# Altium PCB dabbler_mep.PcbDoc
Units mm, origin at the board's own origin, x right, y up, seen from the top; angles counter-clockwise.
Board outline 28 x 70 mm, 2 copper layers (Top Layer, Bottom Layer); 52 components, 40 nets, 219 pads, 126 vias.
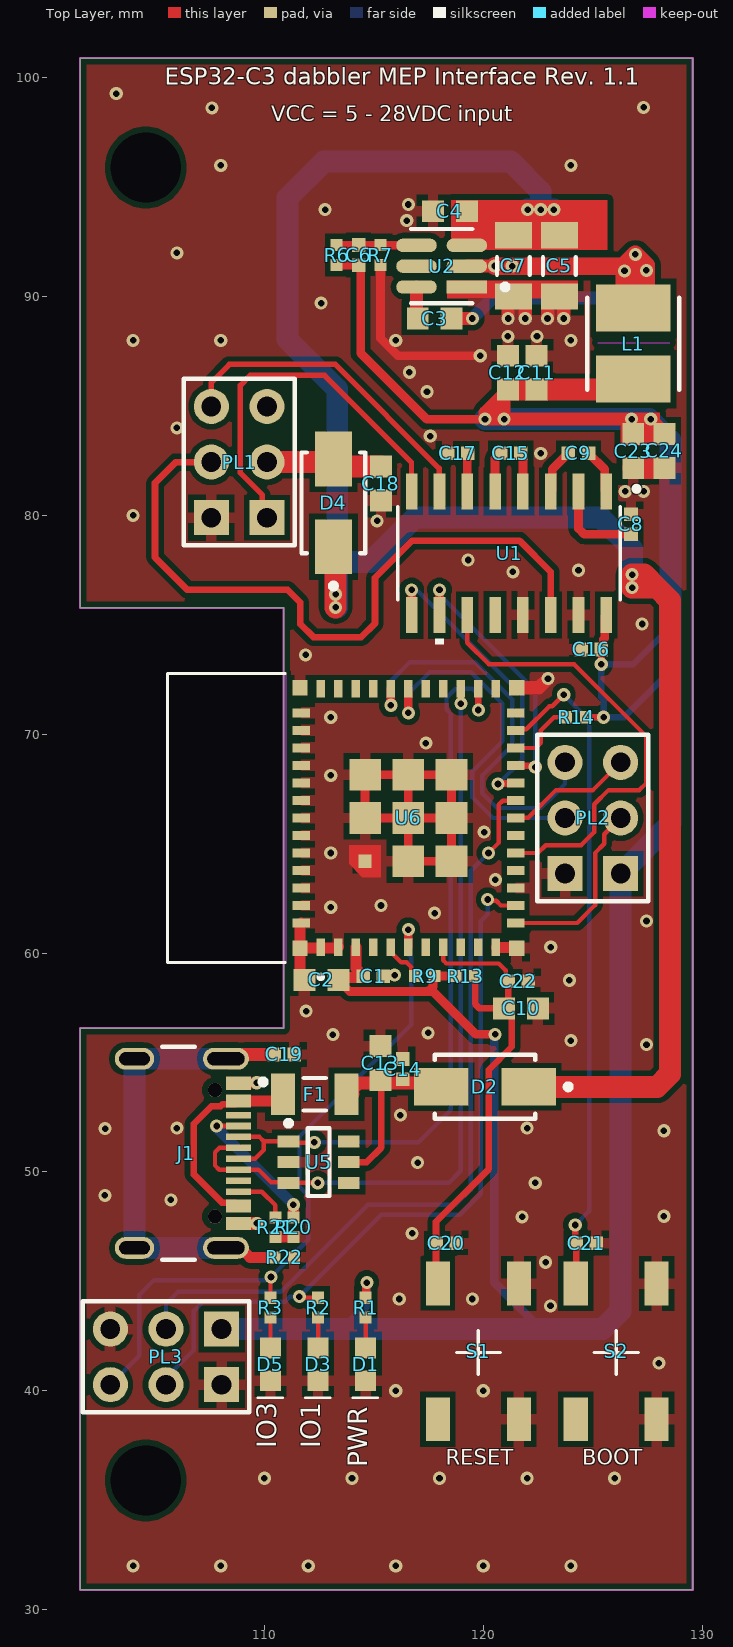
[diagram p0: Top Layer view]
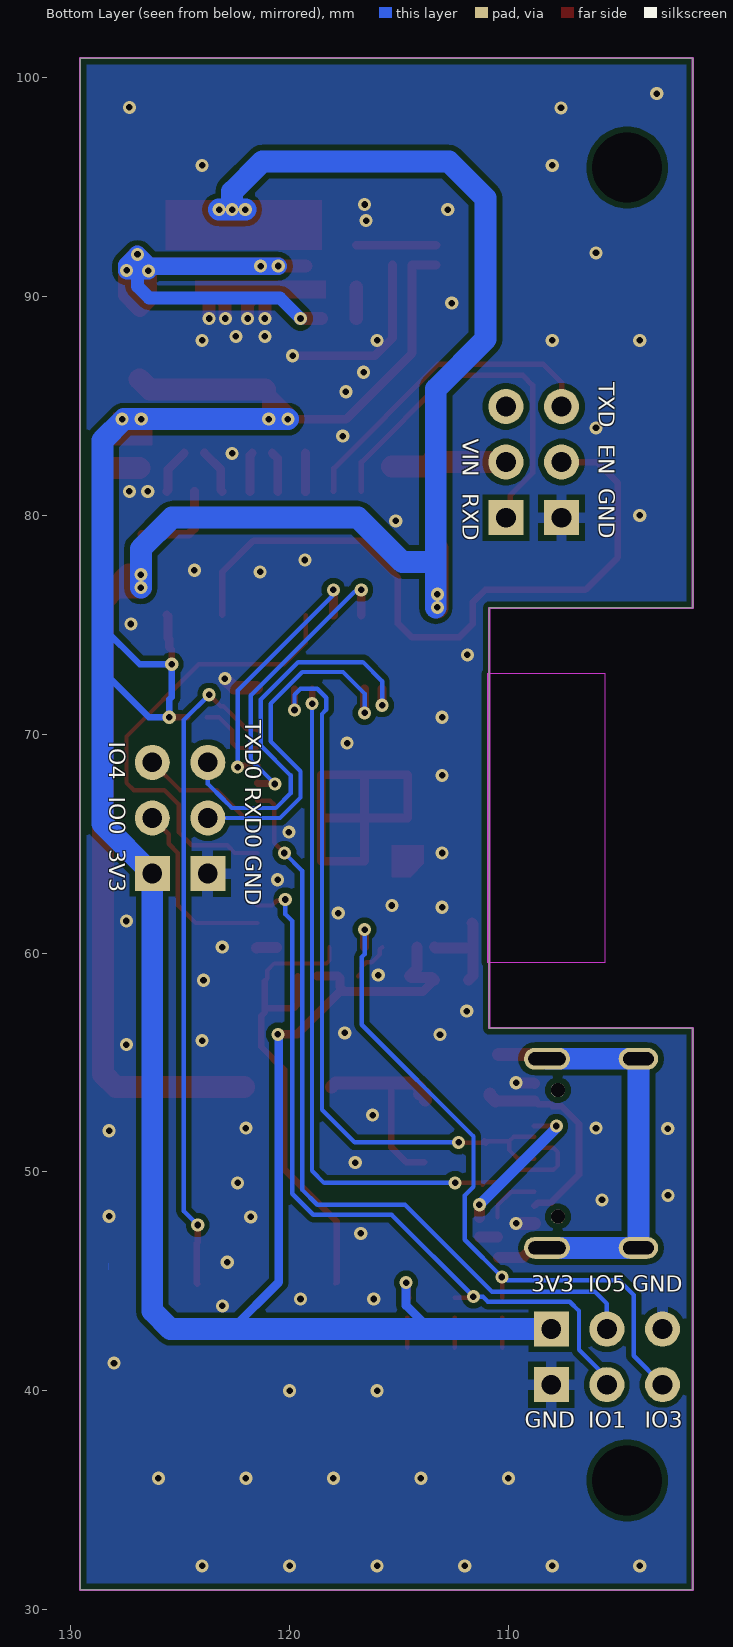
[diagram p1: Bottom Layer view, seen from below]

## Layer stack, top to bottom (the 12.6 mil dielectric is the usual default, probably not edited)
Top Solder: solder mask 0.0102, Solder Resist, Dk 3.5
Top Layer: signal copper 0.0356
Dielectric 1: dielectric 0.32, FR-4, Dk 4.8
Bottom Layer: signal copper 0.0356
Bottom Solder: solder mask 0.0102, Solder Resist, Dk 3.5

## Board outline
101.575,75.775 110.875,75.775 110.875,56.575 101.575,56.575 101.575,30.9 129.575,30.9 129.575,100.9 101.575,100.9

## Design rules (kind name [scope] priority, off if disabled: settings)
Clearance [All] p1: gap=0.254 ignorepadtopadclearanceinfootprint=FALSE except(0: Arc-Hole Track-Hole SMDPad-Hole THPad-Hole Via-Hole Fill-Hole Poly-Hole Region-Hole Text-Hole; 0.2: Arc-SMDPad Arc-THPad Track-SMDPad Track-THPad SMDPad-SMDPad SMDPad-THPad)
PlaneConnect [All] p1: planeconnectstyle=Relief reliefexpansion=0.508 reliefentries=4 reliefconductorwidth=0.5 reliefairgap=0.254
PolygonConnect PolygonConnect_2 [IsVia] p1: connectstyle=Direct reliefconductorwidth=0.254 reliefentries=4 polygonreliefangle="90 Angle" airgapwidth=0.254
PolygonConnect PolygonConnect_1 [(InNet('VBUS') OR InNet('NetF1_2'))] p2: connectstyle=Direct reliefconductorwidth=0.254 reliefentries=4 polygonreliefangle="90 Angle" airgapwidth=0.254
PolygonConnect [All] p3: connectstyle=Relief reliefconductorwidth=0.5 reliefentries=4 polygonreliefangle="90 Angle" airgapwidth=0.254
RoutingVias [All] p1: holewidth=0.711 width=1.27 viastyle="Through Hole" minholewidth=0.711 minwidth=1.27 maxholewidth=0.711 maxwidth=1.27
SolderMaskExpansion [All] p1: expansion=0.102 istentingtop=FALSE
Width [All] p1: maxlimit=1 minlimit=0.2 preferedwidth=0.25 minimp=50.000000 maximp=50.000000 favimp=50.000000
29 further rules are at their usual default settings.

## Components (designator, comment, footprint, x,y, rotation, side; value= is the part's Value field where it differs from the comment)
C1 "0.1uF 0402 10V" CAP_0402 114.975,58.95 r180 top value="100 nF"
C2 "22uF 0603" CAP_0603 112.6,58.775 r0 top value=22uF
C3 "0.1uF 0603 100V" CAP_0603 117.777,89 r180 top value=0.1uF
C4 "0.1uF 0603 100V" CAP_0603 118.477,93.9 r0 top value=0.1uF
C5 "10uF 1206 50V" CAP_1206 123.477,91.4 r90 top value=10uF
C6 "47pF 0402 50V" CAP_0402 114.302,91.9 r270 top value=47pF
C7 "10uF 1206 50V" CAP_1206 121.377,91.4 r90 top value=10uF
C8 "0.1uF 0402 10V" CAP_0402 126.75,79.6 r90 top value="100 nF"
C9 "0.1uF 0402 10V" CAP_0402 124.35,82.85 r180 top value="100 nF"
C10 "22uF 0603" CAP_0603 121.725,57.475 r180 top value=22uF
C11 "22uF 0603" CAP_0603 122.44,86.523 r270 top value=22uF
C12 "22uF 0603" CAP_0603 121.127,86.523 r270 top value=22uF
C13 "22uF 0603" CAP_0603 115.302,54.975 r270 top value=22uF
C14 "0.1uF 0402 10V" CAP_0402 116.327,54.7 r270 top value="100 nF"
C15 "0.1uF 0402 10V" CAP_0402 121.25,82.85 r180 top value="100 nF"
C16 "0.1uF 0402 10V" CAP_0402 124.929,73.875 r0 top value="100 nF"
C17 "0.1uF 0402 10V" CAP_0402 118.825,82.85 r0 top value="100 nF"
C18 "0.1uF 0603 100V" CAP_0603 115.325,81.456 r90 top value=0.1uF
C19 "47pF 0402 50V" CAP_0402 110.906,55.367 r180 top value=47pF
C20 "0.1uF 0402 10V" CAP_0402 118.3,46.75 r180 top value="100 nF"
C21 "0.1uF 0402 10V" CAP_0402 124.7,46.75 r180 top value="100 nF"
C22 "0.1uF 0402 10V" CAP_0402 121.591,58.716 r0 top value="100 nF"
C23 "22uF 0603" CAP_0603 126.852,82.941 r90 top value=22uF
C24 "22uF 0603" CAP_0603 128.275,82.95 r90 top value=22uF
D1 "GREEN LED 0603" "0603 LED" 121.606,25.208 r90 top
D2 "B340A-13-F" FP-SMA-MFG 120.077,53.89 r180 top
D3 "GREEN LED 0603" "0603 LED" 119.433,25.208 r90 top
D4 "B340A-13-F" FP-SMA-MFG 113.15,80.575 r90 top
D5 "GREEN LED 0603" "0603 LED" 117.26,25.208 r90 top
F1 "PTC 500mA Hold" "PTC Fuse 1206" 112.3,53.55 r180 top
J1 "USB4105-GF-A" FP-USB4105-GF-A-MFG 105.225,50.85 r270 top
L1 "6.8uH 1.6A" INDP4040X30N 126.852,87.852 r270 top value=6.8uH
PL1 "2x3-pin Male Header 2.54mm straight" "2x3-pin 2.54mm header" 108.845,82.44 r90 top locked
PL2 "2x3-pin Male Header 2.54mm straight" "2x3-pin 2.54mm header" 125.005,66.175 r90 top
PL3 "2x3-pin Male Header 2.54mm straight" "2x3-pin 2.54mm header" 105.5,41.55 r180 top
R1 "1k 0402" RES_0402 114.625,43.8 r90 top value=1k
R2 "1k 0402" RES_0402 112.45,43.8 r90 top value=1k
R3 "1k 0402" RES_0402 110.275,43.8 r90 top value=1k
R6 "100k 0402" RES_0402 113.302,91.9 r270 top value=100k
R7 "22k1 0402" RES_0402 115.302,91.9 r90 top value=22k1
R9 "10k 0.5% 0402" RES_0402 117.325,58.95 r0 top value=10k
R13 "10k 0.5% 0402" RES_0402 119.175,58.95 r180 top value=10k
R14 "10k 0.5% 0402" RES_0402 124.24,70.779 r0 top value=10k
R20 "4k7 0402" RES_0402 111.325,47.475 r90 top value=4k7
R21 "4k7 0402" RES_0402 110.5,47.475 r90 top value=4k7
R22 "1MOhm 0402 5%" RES_0402 110.9,46.1 r180 top value=1Mega
S1 "TACTB-64K-F" TACTB-64K-F 119.775,41.8 r90 top
S2 "TACTB-64K-F" TACTB-64K-F 126.075,41.8 r90 top
U1 "MAX3232ESE" 21-0041_S16+1_MXM-M 121.175,78.275 r270 top
U2 "TPS54302DDCR" FP-DDC0006A-IPC_A 118.098,91.391 r180 top
U5 "SRV05-" SOT95P280X145-6N 112.475,50.45 r0 top
U6 "ESP32-C3-MINI-1-N4" ESP32-C3-MINI-1-N4-Footprint-1 113.875,66.175 r90 top locked

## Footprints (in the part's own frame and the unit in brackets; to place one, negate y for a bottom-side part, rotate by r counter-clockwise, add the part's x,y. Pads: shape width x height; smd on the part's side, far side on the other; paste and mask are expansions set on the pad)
"2x3-pin 2.54mm header" [mm]
  rect 1.6x1.6 hole 0.9: 1(-2.54,1.27) 2(-2.54,-1.27)
  round 1.6 hole 0.9: 3(0,1.27) 4(0,-1.27) 5(2.54,1.27) 6(2.54,-1.27)
  silkscreen extent -3.81,-2.54 3.81,2.54, body extent -3.81,-2.54 3.81,2.54, height 9.5
21-0041_S16+1_MXM-M [mm]
  rect 1.656x0.533 smd paste+0 mask+0: 1(-2.822,4.445) 2(-2.822,3.175) 3(-2.822,1.905) 4(-2.822,0.635) 5(-2.822,-0.635) 6(-2.822,-1.905) 7(-2.822,-3.175) 8(-2.822,-4.445) 9(2.822,-4.445) 10(2.822,-3.175) 11(2.822,-1.905) 12(2.822,-0.635) 13(2.822,0.635) 14(2.822,1.905) 15(2.822,3.175) 16(2.822,4.445)
  silkscreen extent -2.12,-5.08 4.16,5.08, body extent -3.1,-4.95 3.1,4.95, height 1.76
"0603 LED" [mm] "0603 LED"
  rect 0.95x0.95 smd: 1(16.752,6.985) 2(15.252,6.985)
  silkscreen extent 14.48,6.43 14.48,7.57, body extent 15.2,6.61 16.8,7.39, height 0.7
CAP_0402 [mm] "Chip Capacitor, 2-Leads, 0402, IPC Medium Density"
  rect 0.62x0.62 smd: 1(-0.46,0) 2(0.46,0)
  body extent -0.53,-0.28 0.53,0.28, height 0.4
CAP_0603 [mm] "Chip Capacitor, 2-Leads, 0603, IPC Medium Density"
  rect 1x1 smd: 1(-0.775,0) 2(0.775,0)
  body extent -0.87,-0.48 0.87,0.48, height 0.55
CAP_1206 [mm] "Chip Capacitor, 2-Leads, 1206, IPC Medium Density"
  rect 1.2x1.7 smd: 1(-1.4,0) 2(1.4,0)
  silkscreen extent -0.4,-0.75 0.4,0.75, body extent -1.63,-0.82 1.63,0.82, height 0.7
ESP32-C3-MINI-1-N4-Footprint-1 [mm]
  rect 0.8x0.4 smd: 1(-5.9,1.3) 2(-5.9,0.5) 3(-5.9,-0.3) 4(-5.9,-1.1) 5(-5.9,-1.9) 6(-5.9,-2.7) 7(-5.9,-3.5) 8(-5.9,-4.3) 9(-5.9,-5.1) 10(-5.9,-5.9) 11(-5.9,-6.7) 25(5.9,-6.7) 26(5.9,-5.9) 27(5.9,-5.1) 28(5.9,-4.3) 29(5.9,-3.5) 30(5.9,-2.7) 31(5.9,-1.9) 32(5.9,-1.1) 33(5.9,-0.3) 34(5.9,0.5) 35(5.9,1.3)
  rect 0.4x0.8 smd: 12(-4.8,-7.6) 13(-4,-7.6) 14(-3.2,-7.6) 15(-2.4,-7.6) 16(-1.6,-7.6) 17(-0.8,-7.6) 18(0,-7.6) 19(0.8,-7.6) 20(1.6,-7.6) 21(2.4,-7.6) 22(3.2,-7.6) 23(4,-7.6) 24(4.8,-7.6) 36(4.8,2.2) 37(4,2.2) 38(3.2,2.2) 39(2.4,2.2) 40(1.6,2.2) 41(0.8,2.2) 42(0,2.2) 43(-0.8,2.2) 44(-1.6,2.2) 45(-2.4,2.2) 46(-3.2,2.2) 47(-4,2.2) 48(-4.8,2.2)
  rect 0.6x0.6 smd paste-1 mask+0: 49_1(-1.975,-0.725)
  rect 1.45x1.45 smd: 49_2(0,-0.725) 49_3(1.975,-0.725) 49_4(1.975,-2.7) 49_5(1.975,-4.675) 49_6(0,-4.675) 49_7(-1.975,-4.675) 49_8(-1.975,-2.7) 49_9(0,-2.7)
  rect 0.7x0.7 smd: 50(5.95,2.25) 51(5.95,-7.65) 52(-5.95,-7.65) 53(-5.95,2.25)
  Top Layer region: -1.25,-1.45 -2.7,-1.45 -2.7,-0.6 -2.1,0 -1.25,0
  Keep-Out Layer region: 6.6,2.9 -6.6,2.9 -6.6,8.3 6.6,8.3
  Keep-Out Layer region: 6.6,2.9 -6.6,2.9 -6.6,8.3 6.6,8.3
  silkscreen extent -7.35,1.2 6.6,8.3, body extent -6.6,-8.3 6.6,8.3, height 2.55
FP-DDC0006A-IPC_A [mm]
  rect 1.854x0.612 smd paste+0 mask+0: 1(-1.15,0.95)
  rrect100% 1.854x0.612 smd paste+0 mask+0: 2(-1.15,0) 3(-1.15,-0.95) 4(1.15,-0.95) 5(1.15,0) 6(1.15,0.95)
  silkscreen extent -3.03,-1.7 1.4,1.7, body extent -2.58,-1.95 2.58,1.95, height 0.25
FP-SMA-MFG [mm]
  rect 2.5x1.7 smd paste+0 mask+0: 1(-2,0) 2(2,0)
  silkscreen extent -3.93,-1.46 2.3,1.46, body extent -3.35,-1.56 3.35,1.56, height 0.25
FP-USB4105-GF-A-MFG [mm]
  rrect100% 1x2.1 hole 1.7 slot 0.6 at 0 deg paste-1000 mask+0: 1(-4.32,3.015) 2(4.32,3.015)
  rrect100% 1x1.8 hole 1.4 slot 0.6 at 0 deg paste-1000 mask+0: 3(-4.32,-1.165) 4(4.32,-1.165)
  round 0.65 hole 0.65 unplated paste-1000 mask+0: -(2.89,2.515) --(-2.89,2.515)
  rect 0.6x1.15 smd paste+0 mask+0: A1-B12(-3.2,3.59) A4-B9(-2.4,3.59) B1-A12(3.2,3.59) B4-A9(2.4,3.59)
  rect 0.3x1.15 smd paste+0 mask+0: A5(-1.25,3.59) A6(-0.25,3.59) A7(0.25,3.59) A8(1.25,3.59) B5(1.75,3.59) B6(0.75,3.59) B7(-0.75,3.59) B8(-1.75,3.59)
  silkscreen extent -4.86,0.11 4.86,4.84, body extent -4.96,-3.94 4.96,4.27, height 0.25
INDP4040X30N [mm] "Precision Wire Wound Inductor, 2-Leads, Body 4.00x4.00mm, IPC Medium Density"
  rect 2.15x3.4 smd: 1(-1.625,0) 2(1.625,0)
  silkscreen extent -2.1,-2.1 2.1,2.1, body extent -2.1,-2.1 2.1,2.1, height 3
"PTC Fuse 1206" [mm]
  rect 1.1x1.9 smd: 1(-1.45,0) 2(1.45,0)
  silkscreen extent -0.5,-0.74 0.5,0.74, body extent -1.62,-0.82 1.63,0.83, height 0.4
RES_0402 [mm] "Chip Resistor, 2-Leads, 0402, IPC Medium Density"
  rect 0.55x0.55 smd: 1(-0.45,0) 2(0.45,0)
  body extent -0.53,-0.28 0.53,0.28, height 0.4
SOT95P280X145-6N [mm] "SOT23, 6-Leads, Body 2.93x2.80mm, Pitch 0.95mm, IPC Medium Density"
  rect 1x0.55 smd: 1(-1.375,0.95) 2(-1.375,0) 3(-1.375,-0.95) 4(1.375,-0.95) 5(1.375,0) 6(1.375,0.95)
  silkscreen extent -1.5,-1.55 0.5,1.9, body extent -1.5,-1.53 1.5,1.53, height 1.45
TACTB-64K-F [mm] "Tactile switch"
  rect 2x1.1 smd: 1(-3.1,1.85) 2(3.1,1.85) 3(-3.1,-1.85) 4(3.1,-1.85)
  silkscreen extent -1.05,-1 0.95,1, body extent -3.32,-2.67 3.23,2.68, height 1.6

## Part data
C1 C8 C9 C14 C15 C16 C17 C20 C21 C22: library part CMP-00101-1, "0.1uF 0402 10V X7R 10%", Tolerance="10 %", Voltage="10 V"
C2 C10 C11 C12 C13 C23 C24: library part CMP-00148-1, "Cap Ceramic 22uF 6.3V X5R 20% SMD 0603 85C Cardboard T/R", Capacitance=22uF, Case Code (Imperial)=0603, Case Code (Metric)=1608, Dielectric=X5R, Max Operating Temperature=85°C, Min Operating Temperature=-55°C, Package Quantity=1, Tolerance=20%, Voltage=6.3V
C3 C4 C18: library part CMP-00012-7, "0.1uF 10% 0603 100V X7R", Current Rating=-, Tolerance=10%, Voltage=100V
C5 C7: library part CMP-00030-4, "10uF 1206 50V X5R 20%", Tolerance="+/- 20%", Voltage="50 V"
C6 C19: library part CMP-00099-1, "47pF 0402 50V X7R 5%", Tolerance=10%, Voltage=50V
D1 D3 D5: library part CMP-008-0000-1, "SMD GREEN WATER CLEAR", Mfg. Part Number=APT1608SGC
D2 D4: library part CMP-016-0019-1, "Rectifier Diode, Schottky, 1 Phase, 1 Element, 3A, 40V V(RRM), Silicon", Average Rectified Current=3A, Capacitance=250pF, Case/Package=SMA, Forward Voltage=500mV, Max Forward Surge Current (Ifsm)=80A, Max Operating Temperature=125°C, Max Repetitive Reverse Voltage (Vrrm)=40V, Max Reverse Current=500uA, Min Operating Temperature=-55°C, Package Quantity=5000
F1: library part CMP-017-0001-1, "PTC RESET FUSE 8V 500MA 1206", Case/Package=1206, Mfg. Part Number=0ZCJ0050FF2G
J1: library part CMP-003-0034-0.0, "Conn USB 2.0 Type C RCP 24 POS 0.3mm/0.5mm Solder RA SMD 24 Terminal 1 Port T/R", Flammability Rating="UL94 V-0", Insulation Color=Black, Max Operating Temperature=85°C, Min Operating Temperature=-40°C
L1: library part CMP-00146-1, "6.8UH ±20% 1.6A 117MΩ SMD,4.0X4.0X3.0MM POWER INDUCTORS ROHS", Case/Package=4x4x3mm, Current=1.6A, Mfg. Part Number=SWPA4030S6R8MT
PL1 PL3: library part CMP-003-0019-0.0
PL2: library part CMP-003-0019-0.0, "2x3 Positions Header Connector 0.100\" (2.54mm) Through Hole Gold"
R1 R2 R3: library part CMP-001-0025-3, "RES SMD 1K OHM 1% 1/16W 0402", Case/Package=0402, Mfg. Part Number=CRG0402F1K0, Power=1/16W, Tolerance=1%
R6: library part CMP-00123-1, "Res General Purpose Thick Film 0402 100K Ohm 1% 1/16W ±100ppm/°C Molded SMD Paper T/R", Case Code (Imperial)=0402, Case Code (Metric)=1005, Max Operating Temperature=155°C, Max Power Dissipation=63mW, Mfg. Part Number=RC0402FR-07100KL, Min Operating Temperature=-55°C, Package Quantity=1, Resistance=100kR, Temperature Coefficient=100ppm/°C, Tolerance=1%, Voltage=50V
R7: library part CMP-00147-1, "VISHAY - CRCW040222K1FKEDC. - D10/CRCW0402-C 100 22K1 1% ET7 E3", Case Code (Imperial)=0402, Case Code (Metric)=1005, Max Operating Temperature=155°C, Max Power Dissipation=63mW, Min Operating Temperature=-55°C, Resistance=22.1kR, Resistor Type="Thick Film", Temperature Coefficient=100ppm/°C, Tolerance=1%
R9 R13 R14: library part CMP-0001-00029-2, "RES 10K OHM 0.5% 1/16W 0402", Case/Package=0402, Manufacturer Part No.=RC0402DR-0710KL, Tolerance=0.5%
R20 R21: library part CMP-001-0029-3, "RES SMD 4.7K OHM 1% 1/16W 0402", Case/Package=0402, Mfg. Part Number=RC1005F472CS, Power=1/16W, Tolerance=1
R22: library part CMP-001-0065-1, "RES SMD 1M OHM 5% 1/16W 0402", Case/Package=0402, Mfg. Part Number=CR0402JC1MS001, Power="1/16 W", Tolerance=5%
S1 S2: library part CMP-013-0002-1, "Microswitch TACT; SPST-NO; Positions:2; 0.05A/12VDC;", Case/Package=-
U1: library part CMP-00180-1, "MAX3232 Series 5.5 V 120 kbps Surface Mount RS-232 Transceiver - SOIC-16"
U2: library part CMP-00145-0.0, "BUCK ADJ 3A 6SOT", Case/Package=SOT-23-6, Max Input Voltage=28V, Max Operating Temperature=85°C, Min Input Voltage=4.5V, Min Operating Temperature=-40°C, Min Output Voltage=596mV, Output Current=3A, Quiescent Current=40uA, Switching Frequency=400kHz
U5: library part CMP-016-0020-1, "SRV05 Series 4 Ch 3.5 pF 15 Vclamp Steering Diode/TVS Array Combo - SOT-23-6", Capacitance=3.5pF, Case/Package=SOT-23, Clamping Voltage=15V, Leakage Current=5uA, Max Operating Temperature=150°C, Min Operating Temperature=-55°C, Peak Pulse Current=5A, Peak Pulse Power=500W, Reverse Breakdown Voltage=6V, Reverse Standoff Voltage=5V, Test Current=1mA
U6: library part CMP-00162-1, "Bluetooth, WiFi 802.11b/g/n, Bluetooth v5.0 Transceiver Module 2.412GHz ~ 2.484GHz PCB Trace Surface Mount"

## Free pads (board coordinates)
  round 0 hole 3.2: 3(104.575,35.9) 3(104.575,95.9)

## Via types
v1: diameter 0.6, hole 0.3, Top Layer to Bottom Layer, tented both sides, 126 vias

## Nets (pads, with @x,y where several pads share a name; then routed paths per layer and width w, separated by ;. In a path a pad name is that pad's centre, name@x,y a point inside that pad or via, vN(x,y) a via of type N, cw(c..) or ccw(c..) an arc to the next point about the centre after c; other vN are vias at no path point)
3V3: C1.2 C2.2 C6.2 C11.2 C12.2 C16.2 C23.2 C24.2 L1.2 PL2.2 PL3.2 R1.2 R6.2 R9.2 R13.2 R14.2 U1.16 U6.3 | length 144.2
  Top Layer w0.3: R14.2 v1(125.499,70.779) ; v1(125.389,73.2) C16.2
  Top Layer w0.4: R6.2 114.292,91.45 C6.2 ; C2.2 113.91,58.24 117.466,58.24 ; C6.2@114.402,91.45 114.402,87.415 117.417,84.4 v1(120.077,84.4) ; R1.2 114.651,44.276 114.651,44.92 v1(114.677,44.946) ; R13.2 R9.2 117.7,58.875 117.7,58.474 117.466,58.24 ; v1(120.537,56.289) 119.661,56.289 117.71,58.24 117.466,58.24 ; C16.2@125.499,73.985 125.499,74.344 125.554,74.399 125.554,75.387 U1.16
  Top Layer w0.5: C2.2 113.49,58.89 114.455,58.89 C1.2 114.175,59.29 U6.3
  Top Layer w0.6: C12.2@120.952,85.25 v1(120.952,84.4) ; C12.2 120.952,85.573 C12.2@120.927,85.548 ; C23.2 126.852,83.842 126.779,83.916 v1(126.779,84.4) ; C23.2@126.852,83.725 C24.2@128.075,83.725 ; C24.2 128.075,83.925 128.075,83.979 v1(127.654,84.4) v1(126.779,84.4) ; v1(120.077,84.4) 120.927,85.25 C12.2@120.927,85.548 ; v1(120.077,84.4) v1(120.952,84.4) ; v1(120.077,84.4) 120.077,84.698 C12.2@120.927,85.548 ; v1(120.952,84.4) v1(126.779,84.4)
  Top Layer w1: C12.2 C11.2 126.374,85.748 L1.2
  Bottom Layer w0.3: 128.55,72.9 126.429,70.779 v1(125.499,70.779) 125.499,71.589 125.389,71.699 v1(125.389,73.2) 126.85,73.2 128.5,74.85 128.55,74.85
  Bottom Layer w0.4: 113.575,42.82 113.6,42.82 114.677,43.898 v1(114.677,44.946) ; v1(120.537,56.289) 120.499,56.25 120.499,56.109 120.497,56.108 120.497,44.959 122.637,42.82
  Bottom Layer w1: PL3.2 113.575,42.82 ; 113.6,42.82 122.637,42.82 125.445,42.82 126.275,43.65 PL2.2 128.55,65.91 128.55,72.9 128.55,74.85 128.55,83.425 127.575,84.4 v1(126.779,84.4) v1(120.952,84.4) v1(120.077,84.4)
D+: J1.A6 J1.B6 U5.3 U6.27 | length 35.7
  Top Layer w0.2: J1.A6 107.945,51.1 107.74,50.895 107.74,50.297 107.937,50.1 J1.B6 108.818,50.103 109.722,50.103 110.3,49.525 111.075,49.525 U5.3 ; U5.3@111.187,49.413 U5.3 ; v1(112.437,49.5) U5.3
  Top Layer w0.3: v1(118.975,71.4) U6.27
  Bottom Layer w0.2: v1(112.437,49.5) 118.425,49.5 118.975,50.05 v1(118.975,71.4)
D-: J1.A7 J1.B7 U5.1 U6.26 | length 34.6
  Top Layer w0.2: J1.A7 109.568,50.6 109.971,51.003 109.971,51.4 ; J1.B7 109.771,51.6 109.971,51.4 ; U5.1@111.032,51.332 v1@112.275,51.332 ; U5.1@111.108,51.392 U5.1 109.971,51.4
  Top Layer w0.3: U5.1@111.032,51.332 U5.1 ; U6.26 119.779,72.071 v1(119.779,71.111)
  Bottom Layer w0.2: v1(112.275,51.35) 117.029,51.35 118.521,52.842 118.521,70.929 118.321,71.129 118.321,71.671 118.735,72.084 119.502,72.084 119.779,71.808 v1(119.779,71.111)
ENA: C10.2 C20.2 C22.1 R13.1 S1.2 U6.8 | length 22.2
  Top Layer w0.2: S1.2@117.85,44.975 S1.2 ; U6.8 118.175,59.665 118.315,59.525 120.71,59.525 121.026,59.209 121.026,58.821 C22.1
  Top Layer w0.3: S1.2@117.85,44.975 117.84,44.985 C20.2 117.84,47.723 120.258,50.14 120.258,54.674 121.3,55.717 121.3,57.125 121.131,57.294 C22.1 ; R13.1 119.625,57.676 119.826,57.475 C10.2
ENABLE: PL1.3 U1.14 | length 32.2
  Top Layer w0.3: PL1.3 105.953,82.44 104.998,81.485 104.998,78.082 106.482,76.598 111.062,76.598 111.638,76.022 111.638,75.037 112.236,74.439 114.426,74.439 115.05,75.063 115.05,77.15 116.75,78.85 121.649,78.85 123.08,77.419 U1.14 U1.14@123.077,75.456
ENARS232: U1.11 U6.16 | length 21.4
  Top Layer w0.2: U1.11 119.27,74.188 120.258,73.2 124.15,73.2 127.452,69.898 127.452,67.777 127.125,67.45 125.725,67.45 125.075,66.8 125.075,65.531 124.469,64.925 122.85,64.925 122.5,64.575 U6.16
GND: C1.1 C2.1 C4.1 C5.1 C7.1 C8.2 C10.1 C11.1 C12.1 C13.1 C14.1 C16.1 C17.1 C18.1 C19.1 C20.1 C21.1 C22.2 C23.1 C24.1 D1.2 D3.2 D5.2 J1.A1-B12 J1.B1-A12 PL1.1 PL2.1 PL3.1 PL3.6 R7.1 R20.1 R21.1 R22.1 S1.3 S1.4 S2.3 S2.4 U1.13 U1.15 U2.1 U5.2 U6.1 U6.2 U6.11 U6.14 U6.36 U6.37 U6.38 U6.39 U6.40 U6.41 U6.42 U6.43 U6.44 U6.45 U6.46 U6.47 U6.48 U6.49_1 U6.49_2 U6.49_3 U6.49_4 U6.49_5 U6.49_6 U6.49_7 U6.49_8 U6.49_9 U6.50 U6.51 U6.52 U6.53 | length 43.8
  Top Layer w0.4: R7.1 115.302,88.1 116.104,87.298 v1(119.861,87.298) ; U6.49_9 U6.49_8 U6.49_7 U6.49_6 ; U6.49_9 U6.49_2 U6.49_3 U6.49_4 ; U6.49_9 U6.49_6 ; U6.49_9 U6.49_4 ; U6.49_4 U6.49_5 U6.49_6
  Top Layer w0.5: J1.A1-B12 108.827,54.063 109.637,54.063 v1(109.65,54.075) ; R21.1 R20.1 ; U6.48 111.625,61.325 U6.53 ; C2.1 111.625,58.975 U6.53 ; U6.2 113.325,60.225 U6.53 ; U6.11@120.6,60.25 121.5,60.25 U6.52
  Top Layer w0.6: J1.B1-A12 v1(109.65,47.65) ; v1(121.132,89) 121.132,89.755 C7.1 121.619,90 121.919,89.7 v1(121.919,89) ; U6.51 122.536,72.125 v1(122.957,72.546) ; v1(122.935,89) 122.945,89.01 122.945,89.7 123.245,90 C5.1 123.677,89.8 v1(123.677,89)
  Top Layer w1: C23.1 C24.1@128.266,82.166
  other v1: 104,32 108,32 112,32 116,32 120,32 124,32 110,36 114,36 118,36 122,36 126,36 116,40 120,40 128.025,41.262 123.07,43.88 116.158,44.194 119.502,44.194 122.85,45.871 116.75,47.19 121.775,47.946 128.25,47.978 105.725,48.725 102.71,48.925 122.375,49.5 117,50.425 128.25,51.88 102.721,51.984 106,52 122,52 116.21,52.6 127.459,55.819 124,56 113.127,56.273 117.48,56.356 111.904,57.35 123.936,58.761 115.951,58.994 123.08,60.275 127.459,61.466 117.775,61.829 113.032,62.095 115.325,62.175 120.55,63.35 113.032,64.575 120.035,65.531 113.032,68.121 117.375,69.598 113.032,70.779 111.879,73.625 127.257,75.039 121.352,77.419 124.35,77.497 119.304,77.964 115.15,79.75 104,80 126.486,81.097 127.325,81.097 122.625,82.835 117.575,83.625 106,84 117.428,85.652 116.621,86.544 104,88 108,88 116,88 124,88 121.127,88.184 122.453,88.184 112.591,89.7 106,92 116.503,93.475 112.773,93.975 116.576,94.209 108,96 124,96 107.6,98.625 127.325,98.65 103.225,99.275
IO0: PL2.4 U6.12 | length 8.4
  Top Layer w0.2: U6.12 124.29,61.375 125.11,62.195 125.11,64.575 125.529,64.994 125.529,65.429 PL2.4
IO1: PL3.3 R2.2 U6.13 | length 35.1
  Top Layer w0.2: v1(111.599,44.304) 111.653,44.25 R2.2 ; v1(120.2,62.45) 120.259,62.391 120.59,62.391 120.806,62.175 U6.13
  Bottom Layer w0.2: PL3.3 105.5,40.6 106.775,41.875 106.775,43.65 107.196,44.071 110.941,44.071 111.162,44.293 111.588,44.293 115.341,48.046 118.923,48.046 119.883,49.006 119.883,61.466 120.2,61.783 v1(120.2,62.45)
IO3: PL3.5 R3.2 U6.6 | length 31.7
  Top Layer w0.2: R3.2 110.275,45.175 v1(110.3,45.2)
  Top Layer w0.4: U6.6 v1(116.575,61.075)
  Bottom Layer w0.2: PL3.5 104.275,41.595 104.275,44.375 104.956,45.056 110.048,45.056 110.192,45.2 v1(110.3,45.2) 112,46.9 112,48.925 111.599,49.326 111.599,51.624 116.7,56.725 116.7,59.825 116.575,59.95 v1(116.575,61.075)
IO4: PL2.6 U6.18 | length 5.9
  Top Layer w0.2: U6.18 121.483,66.183 122.058,66.183 123.325,67.45 125.01,67.45 PL2.6
IO5: PL3.4 U6.19 | length 36.2
  Top Layer w0.2: v1(120.238,64.575) 120.7,65.037 120.7,66.775 120.892,66.968 121.468,66.968 U6.19
  Bottom Layer w0.2: PL3.4 105.5,43.975 106.05,44.525 110.752,44.525 114.727,48.5 118.735,48.5 119.429,49.194 119.429,63.766 v1(120.238,64.575)
IO9: C21.2 S2.2 U6.23 | length 30.6
  Top Layer w0.2: U6.23 121.525,70.225 121.962,70.225 123.02,71.283 123.152,71.283 v1(123.677,71.808)
  Top Layer w0.3: v1(124.2,47.575) 124.2,46.79 C21.2 124.24,44.915 S2.2
  Bottom Layer w0.2: v1(123.677,71.808) 124.835,70.651 124.835,48.21 v1(124.2,47.575)
NetC3_1: C3.1 L1.1 U2.2 | length 35.1
  Top Layer w0.6: C3.1 v1(119.502,89) ; U2.2 v1@120.531,91.391
  Top Layer w0.8: v1(120.522,91.4) 120.531,91.391 v1(121.322,91.391) 126.238,91.391 v1(126.452,91.177) ; v1(126.452,91.177) 126.452,89.877 L1.1 L1.1@126.952,89.577 ; v1(126.452,91.177) 126.452,91.427 v1(126.952,91.927) ; L1.1@126.952,89.577 127.452,90.077 v1(127.452,91.198) 127.452,91.427 v1(126.952,91.927) ; L1.1@126.952,89.577 v1(126.952,91.927)
  Bottom Layer w0.5: v1(120.522,91.4) v1@120.527,91.396
  Bottom Layer w0.6: v1(119.502,89) 120.44,89.937 126.415,89.937 126.952,90.475 126.952,91.177 v1(126.952,91.927)
  Bottom Layer w0.8: v1@120.527,91.396 120.531,91.391 v1(121.322,91.391) 126.238,91.391 ; 127.104,91.177 127.431,91.177 v1(127.452,91.198) 127.452,91.427 v1@127.104,91.775 ; 127.104,91.177 v1@127.104,91.775 ; 127.104,91.177 126.952,91.177 v1(126.452,91.177) 126.452,91.427 v1(126.952,91.927) v1@127.104,91.775
NetC3_2: C3.2 U2.6 | length 1.4
  Top Layer w0.6: C3.2@116.952,89 U2.6@116.952,90.436
NetC6_1: C6.1 R6.1 R7.2 U2.4 | length 3.6
  Top Layer w0.4: R6.1 U2.4@116.939,92.35
NetC8_1: C8.1 U1.2 | length 4.2
  Top Layer w0.4: U1.2 124.35,79.404 124.614,79.14 C8.1
NetC9_1: C9.1 U1.1 | length 2.1
  Top Layer w0.4: C9.1 125.554,82.106 125.554,81.163 U1.1
NetC9_2: C9.2 U1.3 | length 2.1
  Top Layer w0.4: U1.3 123.146,81.163 123.146,82.106 C9.2
NetC15_1: C15.1 U1.4 | length 1.8
  Top Layer w0.4: C15.1 121.81,82.75 U1.4
NetC15_2: C15.2 U1.5 | length 1.9
  Top Layer w0.4: U1.5 120.54,82.6 C15.2
NetC17_2: C17.2 U1.6 | length 1.8
  Top Layer w0.4: U1.6 119.27,82.835 C17.2
NetC18_2: C18.2 D4.2 PL1.4 | length 5.5
  Top Layer w1: PL1.4 D4.2@113.265,82.44 ; D4.2@113.4,82.575 D4.2@113.265,82.44 ; C18.2 113.474,82.231 D4.2@113.265,82.44
NetC19_2: C19.2 J1.1 J1.2 J1.3 J1.4 R22.2 | length 21.7
  Top Layer w0.5: J1.2 108.903,46.53 109.333,46.1 R22.2 R22.2@110.446,46.096
  Top Layer w0.6: J1.1 108.898,55.17 109.095,55.367 C19.2
  Bottom Layer w1: J1.2 J1.4 J1.3 J1.1
NetD1_1: D1.1 R1.1 | length 1.4
  Top Layer w0.2: D1.1 114.625,41.964 R1.1
NetD3_1: D3.1 R2.1 | length 1.4
  Top Layer w0.2: D3.1 112.45,41.962 R2.1
NetD5_1: D5.1 R3.1 | length 1.4
  Top Layer w0.2: D5.1 R3.1
NetF1_2: F1.2 J1.A4-B9 J1.B4-A9 | length 9.6
  Top Layer w0.3: J1.B4-A9 108.665,48.6 108.055,48.6 106.775,49.88 106.775,52.2 107.575,53 107.995,53 108.095,53.1 108.24,53.1 108.665,53.1 J1.A4-B9
  Top Layer w0.5: J1.A4-B9 F1.2@110.6,53.25
  Top Layer w0.6: F1.2@110.6,53.25 110.85,53.5 F1.2
NetJ1_A5: J1.A5 R20.2 | length 6.6
  Top Layer w0.25: v1(107.811,52.1) J1.A5
  Top Layer w0.5: R20.2 v1(111.325,48.5)
  Bottom Layer w0.5: v1(107.811,52.1) 107.83,52.081 107.83,51.995 v1(111.325,48.5)
NetJ1_B5: J1.B5 R21.2 | length 2.5
  Top Layer w0.2: J1.B5 109.875,49.1 110.5,48.475 R21.2
NetR9_1: R9.1 U6.5 | length 1.9
  Top Layer w0.2: U6.5 115.875,60.175 115.875,59.951 116.251,59.575 116.5,59.575 116.713,59.362 116.713,59.112 R9.1
NetR14_1: R14.1 U6.22 | length 3.2
  Top Layer w0.2: U6.22 122.388,69.375 122.625,69.612 122.625,70.175 123.229,70.779 R14.1
RXD: PL1.2 U1.8 | length 17.5
  Top Layer w0.25: PL1.2 109.91,80.105 109.91,80.929 108.898,81.94 108.898,85.948 109.346,86.396 112.753,86.396 116.72,82.429 116.72,81.107 U1.8
RXD0: PL2.3 U6.30 | length 16.8
  Top Layer w0.4: v1(116.575,70.975) U6.30
  Bottom Layer w0.2: v1(116.575,70.975) 116.575,71.858 117.563,72.846 119.422,72.846 120.867,71.401 120.867,69.674 119.502,68.309 119.502,67.112 120.44,66.175 PL2.3
ToRX: U1.9 U6.20 | length 13.5
  Top Layer w0.3: v1(120.672,67.727) 120.696,67.751 121.451,67.751 U6.20
  Top Layer w0.4: v1(116.725,76.6) 116.727,76.598 116.727,75.456 U1.9
  Bottom Layer w0.2: v1(116.725,76.6) 116.802,76.523 117.029,76.523 121.775,71.777 121.775,68.83 v1(120.672,67.727)
ToTX: U1.10 U6.21 | length 12
  Top Layer w0.3: U6.21 121.487,68.563 122.231,68.563 122.294,68.5 v1(122.375,68.5)
  Top Layer w0.4: U1.10 v1(118,76.6)
  Bottom Layer w0.2: v1(118,76.6) 118.077,76.523 118.077,76.298 122.375,72 v1(122.375,68.5)
TXD: PL1.5 U1.7 | length 14.9
  Top Layer w0.25: PL1.5 107.575,86.075 108.4,86.9 113.235,86.9 117.982,82.154 117.982,81.115 U1.7
TXD0: PL2.5 U6.31 | length 18.8
  Top Layer w0.4: v1(115.775,71.325) U6.31
  Bottom Layer w0.2: v1(115.775,71.325) 115.775,72.424 116.651,73.3 119.61,73.3 121.321,71.589 121.321,69.486 119.956,68.121 119.956,67.3 120.628,66.629 122.637,66.629 122.907,66.899 cw(c123.735,66.175) 123.011,67.003 123.735,67.727 PL2.5
VBUS: C13.2 C14.2 D2.2 F1.1 U5.5 | length 9.2
  Top Layer w0.3: U5.5 114.677,50.45 115.347,51.119 C13.2@115.347,54.065
  Top Layer w0.6: F1.1@113.802,53.3 F1.1@113.802,53.315 ; F1.1@113.802,53.565 F1.1@114.052,53.565 ; F1.1@114.052,53.815 114.302,54.065 115.347,54.065 117.902,54.065 D2.2
VCC: C4.2 C5.2 C7.2 D2.1 D4.1 U2.3 | length 86.3
  Top Layer w1: v1(113.25,75.8) v1(113.25,76.4) 113.25,78.5 D4.1@113.325,78.575 ; D2.1 127.942,53.89 128.527,54.476 128.527,76.114 127.942,76.7 ; 127.942,76.7 127.342,77.3 v1(126.8,77.3) v1(126.8,76.7) 127.942,76.7
  Bottom Layer w1: v1@113.325,75.8 113.325,76.4 113.325,77.875 ; v1(122.025,93.975) v1(122.625,93.975) ; v1(123.225,93.975) v1(122.625,93.975) ; v1(126.8,76.7) v1(126.8,77.3) 126.8,78.475 125.375,79.9 116.875,79.9 114.85,77.875 113.325,77.875 ; 113.325,77.875 113.325,85.775 111.05,88.05 111.05,94.5 112.725,96.175 121.25,96.175 122.625,94.8 v1(122.625,93.975)
pads on no net: J1.- J1.-- J1.A8 J1.B8 PL1.6 S1.1 S2.1 U1.12 U2.5 U5.4 U5.6 U6.4 U6.7 U6.9 U6.10 U6.15 U6.17 U6.24 U6.25 U6.28 U6.29 U6.32 U6.33 U6.34 U6.35

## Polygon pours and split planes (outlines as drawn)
GND on Bottom Layer "NONET_L-01_P-001" (solid, remove dead copper, pour order 0): 131.175,27.35 132.775,28.95 132.775,104.325 96.875,104.325 92.55,100 96.425,96.125 96.425,28.175
GND on Top Layer "NONET_L-01_P-001" (solid, remove dead copper, pour order 1): 131.175,27.35 132.775,28.95 132.775,104.325 96.875,104.325 92.55,100 96.425,96.125 96.425,28.175

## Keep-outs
Top Layer:
  lines w0.02: 125.227,87.9 128.527,87.9 125.227,87.9
Keep-Out Layer:
  the board outline again, w0.1

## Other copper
Top Layer:
  rectangle net 3V3: 126.275,83.203 128.075,84.698
  region net GND: 124.327,89.925 124.327,90.731 118.338,90.731 118.338,89.925
  region net VCC: 125.677,92.125 125.677,94.425 118.527,94.425 118.527,92.125

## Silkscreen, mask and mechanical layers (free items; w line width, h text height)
Top Overlay:
  text "ESP32-C3 dabbler MEP Interface Rev. 1.1" at 105.45,99.425 h1.3
  text "VCC = 5 - 28VDC input" at 110.3,97.775 h1.2
  text "IO3" at 110.835,37.375 h1.5 r90
  text "IO1" at 112.851,37.375 h1.5 r90
  text "PWR" at 115,36.5 h1.5 r90
  text "RESET" at 118.275,36.4 h1.2
  text "BOOT" at 124.525,36.4 h1.2
Bottom Overlay:
  text "TXD" at 106.115,86.09 h1.25 r90
  text "VIN" at 112.35,83.5 h1.25 r90
  text "EN" at 106.125,83.25 h1.25 r90
  text "GND" at 106.12,81.24 h1.25 r90
  text "RXD" at 112.34,81.015 h1.25 r90
  text "TXD0" at 122.275,70.65 h1.25 r90
  text "IO4" at 128.5,69.65 h1.25 r90
  text "RXD0" at 122.275,67.6 h1.25 r90
  text "IO0" at 128.5,67.15 h1.25 r90
  text "3V3" at 128.5,64.75 h1.25 r90
  text "GND" at 122.275,64.475 h1.25 r90
  text "GND" at 104.35,44.275 h1.25
  text "IO5" at 106.35,44.275 h1.25
  text "3V3" at 108.95,44.275 h1.25
  text "IO3" at 103.775,38.05 h1.25
  text "IO1" at 106.35,38.05 h1.25
  text "GND" at 109.25,38.05 h1.25
Outline:
  lines w0.1: 101.575,75.775 101.575,100.9 129.575,100.9 129.575,30.9 101.575,30.9 101.575,56.575 110.875,56.575 110.875,75.775 101.575,75.775 ; 101.575,75.775 101.575,75.775
Drill Drawing:
  lines w0.1: 127.25,61.425 127.5,61.425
